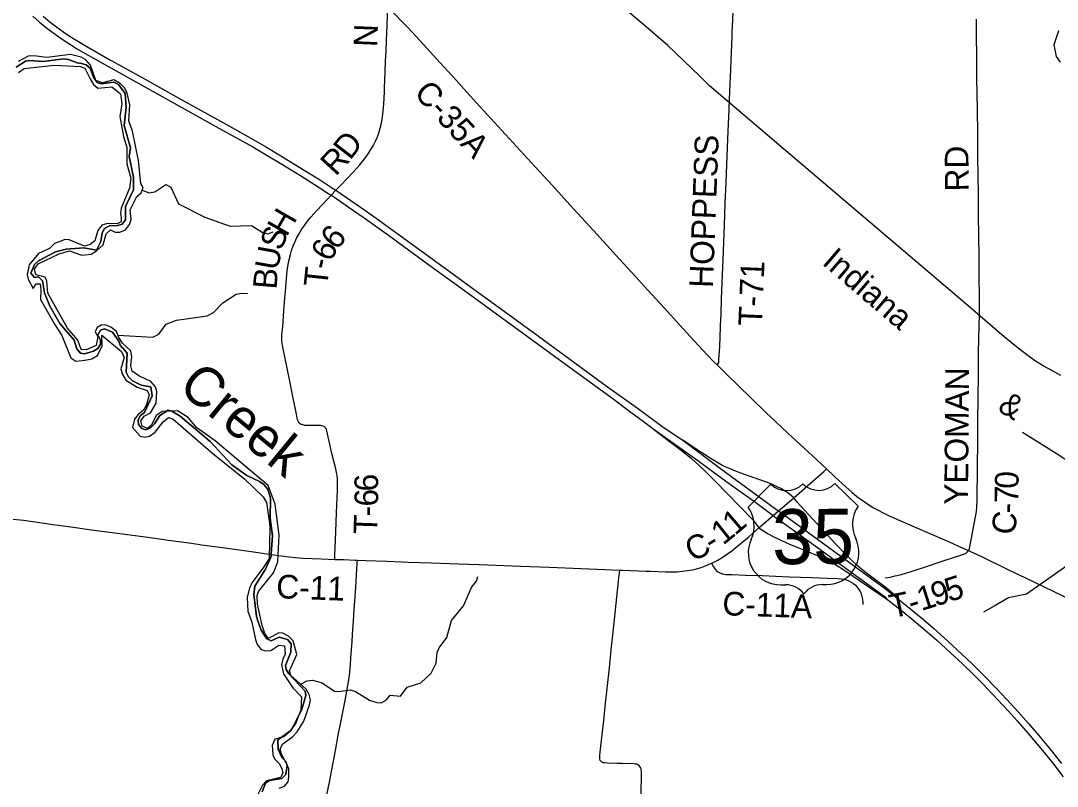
# Model space of a CAD drawing. Extents: x -51392 to 1635000, y 156707 to 696232.
# Drawn here: x 115578 to 128704, y 488186 to 497882 of the extents above; entities that cross this region are included whole.
import ezdxf

# ---------------------------------------------------------------- set-up
doc = ezdxf.new("R2010")
doc.units = 0
for name, color, linetype in [('GM_X_County_Road', 7, 'Continuous'), ('GM_X_County_Road_Text', 7, 'Continuous'), ('GM_X_Interchange_Ramps', 7, 'Continuous'), ('GM_X_Major_River', 7, 'Continuous'), ('GM_X_Minor_River', 7, 'Continuous'), ('GM_X_Minor_River_Text', 7, 'Continuous'), ('GM_X_Rail_Line', 7, 'Continuous'), ('GM_X_Rail_Line_Text', 7, 'Continuous'), ('GM_X_Township', 7, 'Continuous'), ('GM_X_Township_Road', 7, 'Continuous'), ('GM_X_Township_Road_Text', 7, 'Continuous'), ('GM_X_US_Route', 7, 'Continuous'), ('GM_X_US_Shield', 7, 'Continuous')]:
    doc.layers.add(name, color=color, linetype=linetype)

msp = doc.modelspace()

# ---------------------------------------------------------------- linework, layer by layer
at = {"layer": 'GM_X_County_Road'}
for points in [[(120228, 498052), (120267, 498012), (120463, 497813), (120542, 497730), (120719, 497536), (120885, 497355), (121094, 497125), (121227, 496979), (121392, 496797), (121857, 496289), (122089, 496035), (122310, 495793), (122532, 495552), (122830, 495224), (123162, 494862), (123361, 494644), (123516, 494474), (123725, 494244), (123924, 494026), (124101, 493832), (124269, 493652), (124360, 493558), (124395, 493522)], [(127581, 491170), (127591, 491196), (127609, 491283), (127647, 491490), (127674, 491619), (127682, 491668), (127686, 491717), (127689, 491816), (127691, 491963), (127692, 492078), (127695, 492291), (127697, 492488), (127699, 492816), (127702, 493112), (127706, 493391), (127708, 493686), (127714, 494014), (127717, 494162), (127719, 494260), (127718, 494342), (127715, 494687), (127713, 494900), (127711, 495162), (127706, 495425), (127705, 495671), (127702, 495934), (127698, 496147), (127697, 496458), (127693, 496754), (127687, 497164), (127686, 497312), (127684, 497410), (127683, 497516), (127681, 497607), (127680, 497722), (127682, 497902)], [(124395, 493522), (124511, 493408), (124676, 493248), (124818, 493112), (125017, 492917), (125136, 492804), (125292, 492659), (125448, 492513), (125605, 492370), (125781, 492205)], [(125366, 491840), (125400, 491870), (125648, 492086), (125747, 492174), (125781, 492205)], [(125781, 492205), (125884, 492109), (126030, 491976), (126104, 491910), (126167, 491858), (126233, 491809), (126301, 491762), (126370, 491718), (126428, 491686), (126501, 491648), (126575, 491613), (126876, 491481), (127148, 491364), (127343, 491278), (127492, 491210), (127581, 491170)], [(124926, 491461), (125078, 491591), (125106, 491616), (125173, 491674), (125227, 491720), (125366, 491840)], [(115482, 491570), (115612, 491555), (115791, 491530), (115986, 491502), (116181, 491475), (116473, 491435), (116928, 491373), (117189, 491339), (117449, 491304), (117644, 491276), (117741, 491263), (117871, 491245), (118034, 491224), (118196, 491201), (118553, 491149), (118748, 491122), (118750, 491122)], [(124325, 491010), (124348, 491021), (124405, 491051), (124462, 491084), (124516, 491120), (124582, 491169), (124659, 491230), (124796, 491347), (124926, 491461)], [(118750, 491122), (118878, 491104), (118976, 491091), (119057, 491082), (119155, 491076), (119384, 491066), (119556, 491060)], [(119556, 491060), (119663, 491056), (119811, 491051), (119843, 491050)], [(119843, 491050), (119942, 491047), (120220, 491036), (120483, 491026), (120778, 491015), (121122, 491001), (121384, 490993), (121909, 490973), (122269, 490959), (122974, 490931), (123163, 490924)], [(127581, 491170), (127612, 491156), (127717, 491108), (128086, 490929), (128292, 490828), (128781, 490592), (129002, 490485), (129268, 490355), (129415, 490282), (129651, 490167), (129968, 490009)], [(123163, 490924), (123204, 490922), (123496, 490911)], [(123496, 490911), (123548, 490909), (123745, 490902), (123827, 490901), (123892, 490903), (123957, 490909), (124022, 490917), (124086, 490929), (124134, 490940), (124181, 490953), (124228, 490969), (124288, 490993), (124325, 491010)], [(124325, 491010), (124352, 490967), (124369, 490940), (124379, 490927), (124390, 490916), (124402, 490905), (124415, 490896), (124429, 490889), (124443, 490883), (124459, 490878), (124474, 490875), (124507, 490870), (124588, 490867), (124753, 490861), (124966, 490854), (125311, 490840), (125591, 490830), (125788, 490823), (125919, 490818), (125969, 490814), (126002, 490808), (126034, 490799), (126065, 490787), (126094, 490771), (126122, 490752), (126147, 490731), (126170, 490706), (126190, 490680), (126207, 490651), (126215, 490636), (126221, 490620), (126226, 490605), (126234, 490572), (126241, 490523), (126243, 490490)]]:
    msp.add_lwpolyline(points, dxfattribs=at)
at = {"layer": 'GM_X_Interchange_Ramps'}
for points in [[(123583, 492718), (123721, 492609), (123906, 492470), (123984, 492410), (124072, 492336), (124170, 492248), (124254, 492169), (124370, 492052), (124852, 491558), (124926, 491461)], [(125366, 491840), (125290, 491901), (125202, 491956), (125158, 491979), (125099, 492006), (125022, 492036), (124682, 492157), (124590, 492192), (124530, 492218), (124470, 492246), (124413, 492277), (124342, 492319), (124191, 492419), (123962, 492569)], [(126647, 490592), (126625, 490623), (126535, 490698), (126289, 490883), (126226, 490934), (126164, 490988), (126104, 491044), (126000, 491148), (125898, 491254), (125710, 491458), (125455, 491735), (125412, 491784), (125401, 491797), (125366, 491840)], [(124926, 491461), (125041, 491384), (125099, 491353), (125201, 491303), (125306, 491256), (125502, 491175), (125683, 491101), (125758, 491068), (125817, 491040), (125874, 491008), (125943, 490965), (126038, 490902), (126559, 490549)]]:
    msp.add_lwpolyline(points, dxfattribs=at)
at = {"layer": 'GM_X_Major_River'}
msp.add_lwpolyline([(128721, 497754), (128660, 497577), (128690, 497429), (128739, 497359)], dxfattribs=at)
at = {"layer": 'GM_X_Minor_River'}
for points in [[(116615, 497094), (116529, 497123), (116460, 497318), (116401, 497386), (116341, 497421), (116206, 497456), (115909, 497416), (115743, 497437), (115670, 497432), (115545, 497367)], [(115551, 497226), (115621, 497276), (116003, 497319), (116334, 497303), (116388, 497280), (116457, 497145), (116499, 497073), (116553, 497026), (116733, 497045), (116841, 496956), (116858, 496830), (116833, 496671), (116880, 496416), (116921, 496276), (116920, 496071), (116973, 495886), (116954, 495760), (116848, 495508), (116841, 495442), (116849, 495388), (116850, 495336), (116800, 495308), (116676, 495315), (116603, 495291), (116553, 495226), (116518, 495093), (116459, 495048), (116385, 495026), (116193, 495108), (116138, 495110), (116084, 495091), (116004, 495059), (115941, 494997), (115804, 494932), (115683, 494789), (115658, 494669), (115671, 494610), (115735, 494490), (115773, 494550), (115824, 494549), (115833, 494473), (115826, 494353), (116015, 494028), (116098, 493897), (116211, 493614), (116277, 493569), (116355, 493579), (116413, 493586), (116476, 493600), (116548, 493643), (116609, 493763), (116606, 493900), (116855, 493691), (116887, 493615), (116844, 493473), (116864, 493411), (116907, 493330), (117051, 493239), (117179, 493200), (117205, 493143), (117172, 493017), (117134, 492951), (117063, 492894), (117018, 492836), (116992, 492728), (117091, 492621), (117147, 492608), (117208, 492622), (117280, 492670), (117383, 492801), (117450, 492857), (117510, 492834), (118013, 492396), (118410, 492078), (118647, 491852), (118691, 491779), (118722, 491548), (118734, 491462), (118722, 491069), (118657, 490964), (118510, 490766), (118475, 490700), (118446, 490576), (118453, 490405), (118506, 490265), (118551, 490044), (118573, 489982), (118624, 489919), (118678, 489901), (118745, 489906)], [(118973, 488411), (118876, 488604), (118865, 488660), (118895, 488722), (119022, 488818), (119077, 488877), (119162, 489011), (119234, 489217), (119246, 489281), (119231, 489349), (119191, 489416), (118999, 489588), (118980, 489648), (119072, 489856), (119029, 490026), (118967, 490085), (118895, 490124), (118845, 490128), (118714, 490057), (118670, 490119), (118634, 490222), (118576, 490491), (118573, 490601), (118589, 490653), (118690, 490779), (118779, 490890), (118835, 491028), (118851, 491367), (118807, 491690), (118799, 491758), (118712, 491995), (118499, 492173), (118038, 492562), (117806, 492726), (117697, 492855), (117561, 492942), (117370, 492934), (117294, 492882), (117235, 492760), (117184, 492716), (117116, 492747), (117098, 492813), (117141, 492875), (117222, 492917), (117293, 493040), (117302, 493185), (117284, 493247), (117224, 493314), (117072, 493383), (116988, 493442), (116971, 493512), (116977, 493562), (116985, 493622), (116974, 493700), (116866, 493800), (116819, 493868), (116789, 493946), (116719, 494001), (116647, 494032), (116597, 494026), (116546, 493996), (116520, 493942), (116556, 493882), (116535, 493770), (116406, 493715), (116342, 493717), (116302, 493834), (116169, 493989), (115923, 494432), (115908, 494585), (115888, 494635), (115770, 494662), (115753, 494736), (115797, 494804), (116063, 494930), (116196, 494968), (116352, 494914), (116468, 494925), (116539, 494967), (116622, 495043), (116661, 495183), (116713, 495232), (116775, 495206), (116834, 495203), (116906, 495235), (116957, 495301), (116977, 495363), (116964, 495487), (117049, 495657), (117104, 495701), (117128, 495769), (117097, 495819), (117070, 496110), (116991, 496482), (116947, 496614), (116961, 496815), (116926, 496963), (116894, 497030), (116838, 497086), (116758, 497135), (116615, 497094)], [(117117, 495735), (117206, 495704), (117276, 495716), (117416, 495809), (117478, 495776), (117575, 495563), (117911, 495396), (118229, 495279), (118500, 495289), (118636, 495204), (118706, 495184), (118776, 495209)], [(116807, 493899), (117250, 493873), (117327, 493914), (117418, 494038), (117549, 494089), (117673, 494108), (117938, 494145), (118019, 494188), (118138, 494308), (118305, 494419), (118378, 494432), (118450, 494426)], [(128882, 492274), (128702, 492392), (128265, 492666)], [(129574, 491604), (129523, 491546), (129467, 491528), (129395, 491472), (129279, 491429), (129042, 491239), (128839, 490987), (128313, 490618), (128087, 490571), (127906, 490465), (127768, 490389)], [(119126, 489478), (119206, 489522), (119272, 489531), (119396, 489496), (119552, 489391), (119604, 489385), (119749, 489408), (119815, 489387), (119993, 489278), (120087, 489247), (120141, 489242), (120208, 489280), (120254, 489340), (120385, 489325), (120470, 489440), (120645, 489495), (120774, 489619), (120837, 489744), (120852, 489881), (120878, 489939), (120972, 490072), (121031, 490284), (121183, 490472), (121291, 490713), (121348, 490785), (121368, 490843)], [(118745, 489906), (118848, 489972), (118916, 489965), (118927, 489859), (118895, 489797), (118880, 489725), (118905, 489608), (119025, 489431), (119132, 489320), (119125, 489154), (119062, 488986), (118977, 488870), (118908, 488812), (118797, 488781), (118763, 488703), (118770, 488585), (118792, 488533), (118849, 488474), (118885, 488412), (118897, 488353), (118868, 488297), (118689, 488255), (118641, 488201), (118580, 488081)], [(118851, 488163), (118916, 488187), (118966, 488243), (118973, 488301), (118973, 488411)]]:
    msp.add_lwpolyline(points, dxfattribs=at)
at = {"layer": 'GM_X_Rail_Line'}
for points in [[(123772, 497570), (123469, 497830), (122561, 498600), (122001, 499076), (121622, 499400), (121156, 499796), (120756, 500138), (120626, 500251), (120516, 500351), (120067, 500772), (119704, 501118), (119630, 501190), (119566, 501259), (119511, 501324), (119458, 501399), (119399, 501492), (119191, 501912), (118950, 502403), (118418, 503485)], [(124298, 497059), (124179, 497180), (123772, 497570)], [(128749, 493389), (128633, 493450), (128527, 493510), (128428, 493572), (128351, 493624), (128208, 493733), (128033, 493880), (127515, 494322), (125238, 496260), (124298, 497059)]]:
    msp.add_lwpolyline(points, dxfattribs=at)
at = {"layer": 'GM_X_Township'}
for points in [[(115519, 497295), (115637, 497368), (115693, 497379), (115856, 497366), (116125, 497399), (116183, 497393), (116294, 497348), (116348, 497342), (116405, 497325), (116455, 497281), (116499, 497167), (116545, 497101), (116596, 497084), (116758, 497103), (116815, 497076), (116902, 496960), (116912, 496786), (116888, 496557), (116967, 496273), (116952, 496164), (117006, 495902), (117006, 495742), (116903, 495530), (116905, 495362), (116861, 495305), (116807, 495287), (116702, 495286), (116640, 495251), (116611, 495197), (116592, 495086), (116536, 494975), (116377, 495006), (116151, 494990), (116020, 494957), (115802, 494840), (115751, 494794), (115707, 494683), (115752, 494631), (115804, 494638), (115855, 494586), (115880, 494434), (115948, 494266), (116071, 494049), (116253, 493836), (116287, 493727), (116335, 493672), (116386, 493662), (116498, 493697), (116556, 493730), (116587, 493784), (116589, 493838), (116556, 493904), (116588, 493963), (116638, 493979), (116739, 493936), (116818, 493824), (116835, 493774), (116924, 493671), (116914, 493432), (116941, 493372), (116993, 493323), (117104, 493265), (117227, 493244), (117242, 493132), (117146, 492919), (117096, 492880), (117064, 492828), (117071, 492770), (117111, 492716), (117162, 492700), (117220, 492727), (117271, 492775), (117339, 492882), (117443, 492949), (117493, 492938), (117598, 492873), (117975, 492551), (118252, 492257), (118443, 492120), (118600, 492045), (118657, 492009), (118705, 491950), (118742, 491836), (118735, 491583), (118765, 491357), (118750, 491129), (118747, 491094), (118676, 490937), (118542, 490719), (118530, 490615), (118565, 490336), (118582, 490280), (118623, 490164), (118694, 490055), (118747, 490027), (118851, 490074), (118955, 490045), (119004, 489991), (118999, 489883), (118932, 489714), (118939, 489664), (118971, 489610), (119180, 489389), (119189, 489335), (119136, 489164), (119032, 488947), (118996, 488890), (118834, 488772), (118837, 488656), (118883, 488548), (118935, 488499), (118950, 488449), (118933, 488336), (118885, 488284), (118730, 488260), (118679, 488224), (118637, 488115)], [(118637, 488115), (118679, 488224), (118730, 488260), (118885, 488284), (118933, 488336), (118950, 488449), (118935, 488499), (118883, 488548), (118837, 488656), (118834, 488772), (118996, 488890), (119032, 488947), (119136, 489164), (119189, 489335), (119180, 489389), (118971, 489610), (118939, 489664), (118932, 489714), (118999, 489883), (119004, 489991), (118955, 490045), (118851, 490074), (118747, 490027), (118694, 490055), (118623, 490164), (118582, 490280), (118565, 490336), (118530, 490615), (118542, 490719), (118676, 490937), (118747, 491094), (118750, 491129), (118765, 491357), (118735, 491583), (118742, 491836), (118705, 491950), (118657, 492009), (118600, 492045), (118443, 492120), (118252, 492257), (117975, 492551), (117598, 492873), (117493, 492938), (117443, 492949), (117339, 492882), (117271, 492775), (117220, 492727), (117162, 492700), (117111, 492716), (117071, 492770), (117064, 492828), (117096, 492880), (117146, 492919), (117242, 493132), (117227, 493244), (117104, 493265), (116993, 493323), (116941, 493372), (116914, 493432), (116924, 493671), (116835, 493774), (116818, 493824), (116739, 493936), (116638, 493979), (116588, 493963), (116556, 493904), (116589, 493838), (116587, 493784), (116556, 493730), (116498, 493697), (116386, 493662), (116335, 493672), (116287, 493727), (116253, 493836), (116071, 494049), (115948, 494266), (115880, 494434), (115855, 494586), (115804, 494638), (115752, 494631), (115707, 494683), (115751, 494794), (115802, 494840), (116020, 494957), (116151, 494990), (116377, 495006), (116536, 494975), (116592, 495086), (116611, 495197), (116640, 495251), (116702, 495286), (116807, 495287), (116861, 495305), (116905, 495362), (116903, 495530), (117006, 495742), (117006, 495902), (116952, 496164), (116967, 496273), (116888, 496557), (116912, 496786), (116902, 496960), (116815, 497076), (116758, 497103), (116596, 497084), (116545, 497101), (116499, 497167), (116455, 497281), (116405, 497325), (116348, 497342), (116294, 497348), (116183, 497393), (116125, 497399), (115856, 497366), (115693, 497379), (115637, 497368), (115519, 497295)]]:
    msp.add_lwpolyline(points, dxfattribs=at)
at = {"layer": 'GM_X_Township_Road'}
for points in [[(124588, 497745), (124594, 497890), (124602, 498136), (124607, 498267), (124615, 498431), (124628, 498677), (124643, 499005), (124661, 499349), (124675, 499612), (124687, 499858), (124697, 500087), (124704, 500218), (124711, 500333), (124717, 500448), (124724, 500579), (124740, 500890), (124746, 501021), (124748, 501076), (124749, 501088)], [(120185, 497045), (120187, 497124), (120192, 497238), (120198, 497369), (120204, 497501), (120208, 497632), (120212, 497730), (120217, 497828), (120223, 497943), (120227, 498025), (120228, 498052)], [(124440, 494021), (124446, 494167), (124453, 494364), (124462, 494561), (124472, 494856), (124484, 495184), (124492, 495414), (124500, 495578), (124506, 495742), (124514, 495941), (124523, 496168), (124532, 496381), (124540, 496578), (124549, 496759), (124554, 496890), (124566, 497169), (124578, 497480), (124585, 497677), (124588, 497745)], [(118930, 494453), (118944, 494616), (118953, 494714), (118965, 494795), (118977, 494859), (118993, 494923), (119007, 494970), (119029, 495032), (119048, 495077), (119076, 495137), (119100, 495180), (119134, 495236), (119170, 495290), (119210, 495342), (119252, 495393), (119329, 495478), (119464, 495622), (119510, 495671), (119569, 495734), (119632, 495801), (119790, 495969), (119867, 496053), (119920, 496116), (119959, 496169), (119987, 496209), (120013, 496251), (120045, 496308), (120074, 496367), (120094, 496412), (120111, 496458), (120130, 496521), (120143, 496569), (120156, 496633), (120165, 496698), (120173, 496779), (120180, 496894), (120183, 496992), (120185, 497045)], [(119556, 491060), (119557, 491112), (119559, 491210), (119567, 491407), (119578, 491653), (119589, 491931), (119590, 492030), (119588, 492079), (119583, 492128), (119577, 492160), (119566, 492208), (119519, 492399), (119478, 492575), (119454, 492687), (119450, 492703), (119444, 492718), (119434, 492731), (119421, 492741), (119407, 492748), (119391, 492752), (119375, 492754), (119325, 492755), (119210, 492755), (119177, 492756), (119161, 492759), (119145, 492763), (119130, 492769), (119117, 492778), (119105, 492789), (119095, 492803), (119088, 492817), (119083, 492833), (119079, 492849), (119069, 492897), (119025, 493123), (118986, 493316), (118955, 493460), (118925, 493605), (118895, 493749), (118887, 493798), (118884, 493830), (118884, 493847), (118886, 493896), (118895, 494010), (118911, 494207), (118924, 494370), (118930, 494453)], [(124395, 493522), (124413, 493544), (124417, 493559), (124420, 493593), (124429, 493757), (124439, 494003), (124440, 494021)], [(119456, 488076), (119486, 488237), (119562, 488640), (119599, 488833), (119627, 488978), (119680, 489252), (119728, 489510), (119741, 489591), (119749, 489672), (119763, 489868), (119774, 490015), (119781, 490113), (119792, 490277), (119801, 490424), (119812, 490588), (119820, 490702), (119840, 491013), (119843, 491050)], [(126524, 490825), (126588, 490836), (126653, 490850), (126732, 490870), (126841, 490903), (127059, 490974), (127246, 491036), (127402, 491086), (127495, 491116), (127519, 491124), (127530, 491128), (127541, 491134), (127550, 491140), (127558, 491146), (127566, 491154), (127581, 491170)], [(123436, 488047), (123437, 488376), (123435, 488392), (123433, 488408), (123427, 488423), (123419, 488437), (123408, 488449), (123394, 488458), (123379, 488464), (123363, 488467), (123346, 488469), (123199, 488473), (123133, 488475), (123002, 488479), (122969, 488481), (122953, 488483), (122938, 488489), (122926, 488499), (122917, 488513), (122912, 488529), (122910, 488545), (122910, 488561), (122912, 488578), (122924, 488692), (122960, 489018), (122979, 489197), (123004, 489425), (123032, 489686), (123055, 489914), (123092, 490256), (123151, 490827), (123159, 490892), (123163, 490924)]]:
    msp.add_lwpolyline(points, dxfattribs=at)
at = {"layer": 'GM_X_US_Route'}
for points in [[(115729, 497941), (115816, 497866), (115905, 497793), (115996, 497724), (116089, 497657), (116185, 497593), (116282, 497532), (116395, 497465), (116824, 497225), (117799, 496682), (118085, 496522), (118516, 496284), (118686, 496185), (118884, 496067), (119121, 495921), (119356, 495771), (119480, 495691), (119510, 495671), (119549, 495646), (119726, 495527), (119928, 495386), (120234, 495165), (120804, 494749), (121149, 494499), (122289, 493667), (122754, 493329), (123045, 493117), (123321, 492910), (123441, 492824), (123583, 492718), (124151, 492311), (124363, 492157), (124655, 491945), (124868, 491791), (125106, 491616), (125145, 491587), (125410, 491394), (125742, 491154), (125891, 491046)], [(115863, 497938), (115952, 497865), (116030, 497805), (116123, 497738), (116204, 497683), (116288, 497630), (116415, 497554), (116686, 497400), (117144, 497145), (117617, 496881), (118190, 496562), (118463, 496411), (118690, 496280), (118873, 496171), (119167, 495991), (119361, 495869), (119513, 495771), (119569, 495734), (119581, 495726), (119690, 495653), (119893, 495514), (120080, 495381), (120956, 494744), (121287, 494502), (121884, 494069), (122135, 493885), (123010, 493247), (123382, 492977), (123726, 492725), (123962, 492569), (124421, 492222), (124646, 492057), (124911, 491864), (125137, 491700), (125173, 491674), (125403, 491508), (125668, 491315), (126025, 491053), (126356, 490812), (126529, 490688), (126647, 490592), (126661, 490580), (126848, 490430), (127012, 490294), (127136, 490187), (127319, 490023), (127500, 489856), (127619, 489743), (127770, 489593), (127930, 489429), (128066, 489286), (128209, 489129), (128339, 488981), (128467, 488831), (128613, 488654), (128756, 488475)], [(125891, 491046), (126061, 490923), (126449, 490638), (126526, 490585), (126559, 490549)], [(126559, 490549), (126727, 490417), (126867, 490303), (127029, 490165), (127177, 490035), (127347, 489880), (127503, 489735), (127645, 489598), (127760, 489482), (127885, 489351), (128086, 489135), (128196, 489013), (128336, 488852), (128536, 488613), (128659, 488460), (128780, 488304)]]:
    msp.add_lwpolyline(points, dxfattribs=at)
at = {"layer": 'GM_X_US_Shield'}
for p, q in [((125077, 492012), (124790, 491719)), ((126182, 491732), (125889, 492019)), ((125205, 490737), (125263, 490737)), ((125727, 490741), (125785, 490742))]:
    msp.add_line(p, q, dxfattribs=at)
for centre, radius, start, end in [((125278, 492221), 290, 226.1115, 314.9656), ((125684, 492224), 290, 226.1115, 314.9656), ((124459, 491483), 406, 335.0857, 35.5395), ((126517, 491502), 406, 145.5376, 205.9914), ((125197, 491143), 406, 155.3705, 271.1768), ((125786, 491148), 406, 269.9003, 25.7066), ((125266, 490447), 290, 37.4084, 90.5385), ((125730, 490451), 290, 90.5385, 143.6686)]:
    msp.add_arc(centre, radius, start, end, dxfattribs=at)

# ---------------------------------------------------------------- texts
at = {"layer": 'GM_X_County_Road_Text'}
for s, rotation, p in [('C-35A', 312.5068, (120545, 496956)), ('RD', 90.5385, (127583, 495721)), ('YEOMAN', 89.4606, (127572, 491750)), ('0', 88.8485, (128212, 491952)), ('7', 88.7881, (128208, 491767)), ('-', 87.1658, (128201, 491635)), ('1', 40.4878, (124623, 491354)), ('C', 80.9472, (128159, 491356)), ('1', 38.5519, (124471, 491232)), ('C', 24.9663, (124079, 491025)), ('-', 31.2155, (124332, 491145)), ('C-11', 357.7821, (118809, 490569)), ('C-11A', 358.0162, (124459, 490353))]:
    msp.add_text(s, height=300, rotation=rotation, dxfattribs=at).set_placement(p)
at = {"layer": 'GM_X_Minor_River_Text'}
msp.add_text('Creek', height=500, rotation=320.5311, dxfattribs=at).set_placement((117553, 493212))
at = {"layer": 'GM_X_Rail_Line_Text'}
for s, rotation, p in [('Indiana', 319.4337, (125713, 494805)), ('&', 328.6272, (127934, 492951))]:
    msp.add_text(s, height=299, rotation=rotation, dxfattribs=at).set_placement(p)
at = {"layer": 'GM_X_Township_Road_Text'}
for s, rotation, p in [('N', 87.674, (120090, 497545)), ('D', 52.347, (119750, 496106)), ('HOPPESS', 87.8176, (124343, 494495)), ('R', 47.4239, (119566, 495903)), ('H', 60.0965, (118944, 495135)), ('S', 69.3212, (118878, 494957)), ('6', 50.1506, (119578, 494965)), ('6', 62.7679, (119503, 494816)), ('U', 79.873, (118836, 494711)), ('-', 76.2865, (119480, 494713)), ('B', 85.2385, (118816, 494473)), ('T', 83.894, (119458, 494501)), ('T-71', 87.7113, (124964, 494012)), ('6', 90.7909, (120105, 491922)), ('6', 88.9937, (120102, 491727)), ('-', 88.3427, (120098, 491600)), ('T', 88.1722, (120091, 491375)), ('9', 17.7643, (127158, 490460)), ('5', 17.8178, (127334, 490516)), ('T', 11.6913, (126611, 490313)), ('1', 17.5259, (126981, 490404)), ('-', 17.2068, (126861, 490367))]:
    msp.add_text(s, height=300, rotation=rotation, dxfattribs=at).set_placement(p)
at = {"layer": 'GM_X_US_Shield'}
msp.add_text('35', height=696.1, rotation=0.5385, dxfattribs=at).set_placement((125096, 490997))

doc.saveas('drawing.dxf')
